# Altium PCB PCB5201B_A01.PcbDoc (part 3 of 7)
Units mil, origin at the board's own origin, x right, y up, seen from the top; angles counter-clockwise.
Board outline 4527.56 x 2362.2 mil, 6 copper layers (Top Layer, GND Layer 2, Signal Layer 3, Signal Layer 4, VCC Layer 5, Bottom Layer), stack 61.221 mil thick; 361 components, 250 nets, 1223 pads, 1068 vias.
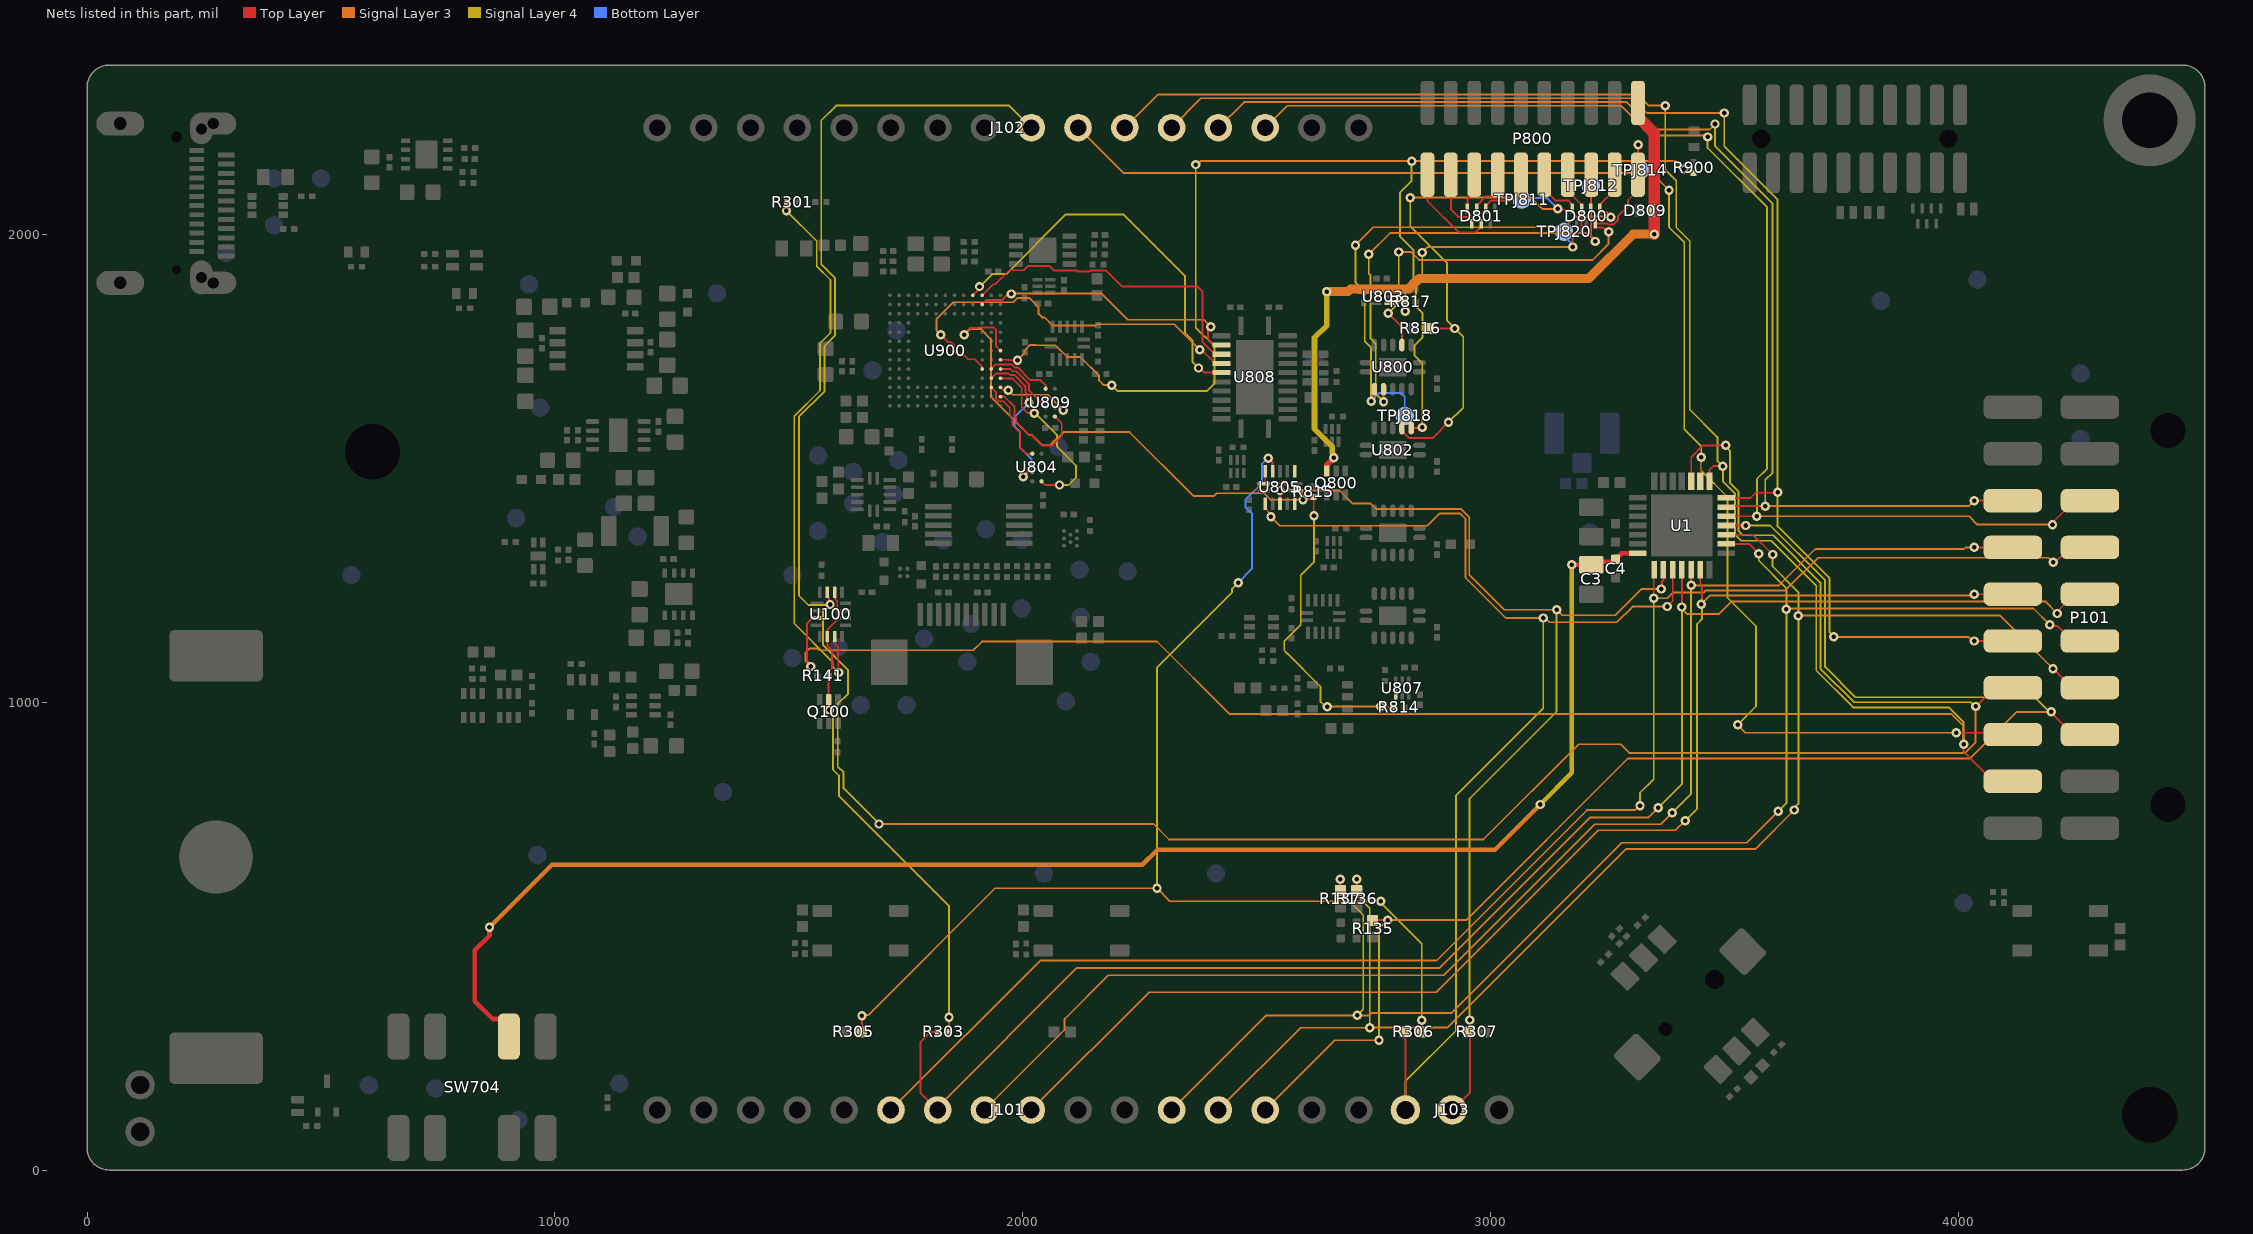
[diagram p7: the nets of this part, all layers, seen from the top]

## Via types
v1: diameter 20, hole 9.84, Top Layer to Bottom Layer, tented both sides, 1068 vias

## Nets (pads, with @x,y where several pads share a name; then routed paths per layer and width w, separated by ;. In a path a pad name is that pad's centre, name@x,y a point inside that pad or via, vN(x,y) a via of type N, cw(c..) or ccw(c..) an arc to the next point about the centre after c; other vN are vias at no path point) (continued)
DEBUG_DH_SW_ENABLE: R817.2 R900.1 U803.4 U900.F1 | length 2496.7
  Top Layer w3.94: U900.F1@1952.76,1732.28 1970.47,1732.28 1971.46,1731.3 1989.04,1731.3 v1(1989.11,1731.37) ; U803.4@2784.45,1853.35 2785.93,1854.82 2815.45,1854.82 R817.2@2817.91,1857.28 ; R817.2@2816.93,1856.3 2817.5,1855.72 2817.5,1836.91 v1(2818.08,1836.33) ; v1(3413.39,2139.76) 3414.86,2139.76 3423.11,2131.51 R900.1@3434.43,2131.51
  Signal Layer 3 w3.94: v1(1989.11,1731.37) 2004.7,1746.96 2004.7,1752.53 2016.2,1764.02 2027.14,1764.02 2027.81,1763.35 2070,1763.35 2095.16,1738.19 2123.11,1738.19 2163.39,1697.92 2163.39,1687.99 2173.23,1678.15 v1(2190.77,1678.15) ; v1(2370.08,2149.61) 2373.09,2149.61 2380.42,2156.94 v1(2831.64,2156.94) 3396.21,2156.94 v1(3413.39,2139.76)
  Signal Layer 4 w3.94: v1(2190.77,1678.15) 2203.56,1665.35 2394.11,1665.35 2410.43,1681.68 2410.43,1760.83 2370.08,1801.18 v1(2370.08,2149.61) ; v1@2815.94,1836.61 2818.19,1838.86 2818.19,1887.85 2835.35,1905.01 2835.35,1967.41 2807.09,1995.67 2807.09,2090.55 2831.64,2115.11 v1(2831.64,2156.94)
DEBUG_MCU_SW_ENABLE: R814.2 R815.2 U805.5 U805.6 U805.12 U805.13 U807.4 U900.G1 | length 1977.7
  Top Layer w3.94: v1(1875,1785.43) 1875,1787.4 1888.08,1800.48 1905.03,1800.48 1905.73,1801.18 1937.99,1801.18 1942.91,1796.26 1942.91,1761.81 U900.G1@1952.76,1751.97 ; U805.13@2515.35,1467.32 2518.7,1470.67 U805.12@2518.7,1494.29 ; U805.13@2517.52,1469.49 2557.09,1469.49 2575,1451.57 U805.6@2585.04,1451.57 ; U805.5@2581.69,1424.61 2581.69,1448.23 U805.6@2585.04,1451.57 ; v1(2623.03,1398.62) 2622.35,1399.31 2622.35,1437.98 R815.2@2621.66,1438.67 2621.66,1438.27 2617.33,1433.94 2600.28,1433.94 v1(2599.41,1433.07) 2598.61,1433.87 2598.61,1446.67 2596.46,1448.82 2596.46,1449.61 2594.49,1451.57 U805.6@2585.04,1451.57 ; v1(2765.75,991.14) 2766.63,990.26 2791.71,990.26 R814.2@2792.6,989.37 ; R814.2@2792.32,991.14 2794.76,991.14 2797.76,994.13 U807.4@2797.76,1016.73
  Signal Layer 3 w3.94: v1(1875,1785.43) 1887.8,1798.23 1910.43,1798.23 1932.09,1776.57 1932.09,1653.32 2014.26,1571.15 2020.17,1571.15 2041.82,1549.49 2059.44,1549.49 2087.7,1577.76 2228.49,1577.76 2365.02,1441.22 2409.73,1441.22 2415.35,1446.85 2516.17,1446.85 2529.95,1433.07 v1(2599.41,1433.07) ; v1@2654.53,991.14 2654.78,990.89 2765.5,990.89 v1(2765.75,991.14)
  Signal Layer 4 w3.94: v1(2623.03,1398.62) 2623.03,1300.2 2594.77,1271.93 2594.77,1165.63 2559.33,1130.2 2559.33,1110.72 2566,1104.05 2566.45,1104.05 2636.81,1033.69 2636.81,1000.98 2647.15,990.64 v1(2651.25,990.64)
DEBUG_RESET_#OE: U804.A1 U900.D1 | length 386.7
  Top Layer w3.94: U900.D1@1952.76,1692.91 1953.74,1691.93 1978.35,1691.93 1998.03,1672.24 1998.03,1630.91 2010.83,1618.11 v1(2024.61,1618.11) ; U804.A1@2040.35,1472.44 2048.23,1464.57 v1(2078.74,1464.57)
  Signal Layer 4 w3.94: v1(2024.61,1618.11) 2026.57,1618.11 2073.82,1570.87 2073.82,1546.48 2114.17,1506.13 2114.17,1480.32 2098.43,1464.57 v1(2078.74,1464.57)
DEBUG_TCK_SWCLK_#OE: U809.A1 U900.B1 | length 248.4
  Top Layer w3.94: U900.B1@1952.76,1653.54 1961.32,1653.54 1982.28,1632.58 1982.28,1613.19 1986.5,1608.97 1986.5,1598.91 1986.71,1598.7 1986.71,1597.93 2013.78,1570.87 2019.69,1570.87 2041.34,1549.21 2063.98,1549.21 2083.66,1568.9 2083.66,1596.46 U809.A1@2068.9,1611.22
DEBUG_TCK_SWCLK_C2CK: J103.2 R307.2 U1.9 U805.3 | length 2251.8
  Top Layer w3.94: U805.3@2550.2,1424.61 v1@2550.2,1446.85 ; J103.2@2918.5,128.43 2956.69,166.61 2956.69,295.28 2955.71,296.26 v1(2955.71,320.87) ; v1(3365.16,1242.13) 3366.79,1243.76 3366.79,1258.03 3370.08,1261.32 U1.9@3370.08,1288.39
  Signal Layer 3 w3.94: v1@2552.17,1452.76 2678.15,1452.76 2705.99,1424.92 2744.37,1424.92 2755.91,1413.39 2936.7,1413.39 2954.72,1395.36 2954.72,1272.64 3029.53,1197.83 v1(3141.73,1197.83) 3153.54,1186.02 3266.73,1186.02 3322.83,1242.13 v1(3365.16,1242.13)
  Signal Layer 4 w3.94: v1(2955.71,320.87) 2955.71,794.29 3141.73,980.32 v1(3141.73,1197.83)
  other v1: 2550.2,1452.76
DEBUG_TCK_SWCLK_IN: U808.4 U900.N3 | length 681.6
  Top Layer w3.94: U900.N3@1913.39,1870.08 1937.01,1893.7 1941.93,1893.7 1971.91,1923.68 1997.14,1923.68 1997.18,1923.73 2002.47,1923.73 2011.81,1933.07 2057.09,1933.07 2066.73,1923.43 2115.45,1923.43 2117.68,1921.19 2144.54,1921.19 2146.58,1923.23 2177.92,1923.23 2212.55,1888.6 2374.32,1888.6 2384.84,1878.08 2384.84,1769.69 2410.43,1744.09 U808.4@2425.39,1744.09
DEBUG_TCK_SWCLK_OUT: U809.B1 U900.C1 | length 175.8
  Top Layer w3.94: U900.C1@1952.76,1673.23 1958.66,1667.32 v1(1969.49,1667.32) v1@1970.47,1666.34 ; U809.B1@2068.9,1630.91 2076.28,1630.91 2082.67,1624.51 v1(2086.61,1624.51)
  Signal Layer 3 w3.94: v1(1969.49,1667.32) 1979.33,1657.48 2053.64,1657.48 v1(2086.61,1624.51)
DEBUG_TDI_#OE: U809.B2 U900.E1 | length 138.3
  Top Layer w3.94: U900.E1@1952.76,1712.6 1973.42,1712.6 1978.35,1707.68 1986.16,1707.68 2013.9,1679.94 2013.9,1666.22 U809.B2@2049.21,1630.91
DEBUG_TDI_C2DPS: R305.1 R306.1 U805.11 | length 2646.6
  Top Layer w3.94: R305.1@1655.51,295.28 1656.5,296.26 v1(1656.5,329.72) ; v1(2525.29,1521.64) 2526.05,1521.64 2534.45,1513.24 U805.11@2534.45,1494.29 ; R306.1@2851.38,295.28 2853.35,297.24 v1(2853.35,319.88)
  Signal Layer 3 w3.94: v1(1656.5,329.72) 1657.9,331.13 1669.71,331.13 1940.94,602.36 v1(2287.4,602.36) 2314.96,574.8 v1(2765.75,574.8)
  Signal Layer 4 w3.94: v1(2287.4,602.36) 2287.4,1074.8 2447.83,1235.24 2447.83,1243.11 v1(2460.63,1255.91) ; v1(2765.75,574.8) 2765.75,571.8 2853.35,484.2 v1(2853.35,319.88)
  Bottom Layer w3.94: v1(2460.63,1255.91) 2490.16,1285.43 2490.16,1402.56 ; 2490.65,1403.05 2476.38,1417.32 2476.38,1433.07 2511.81,1468.5 2511.81,1509.84 2523.61,1521.64 v1(2525.29,1521.64)
DEBUG_TDI_IN: U808.6 U900.N4 | length 844
  Top Layer w3.94: U900.N4@1893.7,1870.08 1907.91,1884.28 v1(1907.91,1888.78) ; v1(2376.12,1714.74) 2378.59,1714.74 2388.6,1704.72 U808.6@2425.39,1704.72
  Signal Layer 4 w3.94: v1(1907.91,1888.78) 1934.61,1915.48 1964.69,1915.48 2092.33,2043.12 2214.76,2043.12 2347.44,1910.43 2347.44,1789.37 2363.42,1773.39 2363.42,1727.44 v1(2376.12,1714.74)
DEBUG_TDI_OUT: U809.D2 U900.E2 | length 146.1
  Top Layer w3.94: U900.E2@1933.07,1712.6 1942.91,1722.44 1976.16,1722.44 1982.77,1715.83 1989.15,1715.83 2016.09,1688.88 2037.88,1688.88 2049.21,1677.55 U809.D2@2049.21,1670.28
DEBUG_TDO_SWO: U805.8
DEBUG_TDO_SWO_IN: U808.5 U900.E3 | length 863.7
  Top Layer w3.94: v1(1824.8,1785.43) 1840.55,1769.69 1847.25,1769.69 1853.74,1763.19 1853.74,1750.59 1863.19,1741.14 1875.79,1741.14 1883.67,1733.27 1897.64,1733.27 1913.39,1717.52 U900.E3@1913.39,1712.6 ; v1(2378.89,1753.41) 2382.41,1753.41 2411.42,1724.41 U808.5@2425.39,1724.41
  Signal Layer 3 w3.94: v1(1824.8,1785.43) 1815.94,1794.29 1815.94,1819.88 1851.38,1855.32 1980.09,1855.32 1988.94,1864.17 2015.09,1864.17 2034.29,1844.97 2034.29,1830.23 2041.69,1822.83 2046.74,1822.83 2064.18,1805.4 2155.48,1805.4 2158.16,1808.07 2324.23,1808.07 v1(2378.89,1753.41)
DEBUG_TMS_SWDIO_#OE: U804.B2 U900.D2 | length 346.3
  Top Layer w3.94: U900.D2@1933.07,1692.91 1942.91,1702.76 1970.47,1702.76 1973.43,1699.8 1982.28,1699.8 2006.03,1676.06 2006.03,1662.61 2008.86,1659.77 2008.86,1645.66 v1(2013.78,1640.75) ; v1@1999.02,1482.28 2008.86,1492.13 U804.B2@2020.67,1492.13
  Bottom Layer w3.94: v1(2000.98,1482.28) 2018.7,1500 2018.7,1520.67 1995.08,1544.29 1995.08,1577.76 1982.28,1590.55 1982.28,1609.25 v1(2013.78,1640.75)
DEBUG_TMS_SWDIO_C2D: J103.1 R306.2 U1.10 U805.1 | length 2508.2
  Top Layer w3.94: U805.1@2518.7,1424.61 2518.7,1414.37 v1@2530.9,1402.17 ; R306.2@2815.94,292.32 2818.5,289.76 J103.1@2818.5,128.43 2818.5,126.57 J103.1@2816.93,125 ; v1(3377.95,1204.72) 3389.76,1216.54 U1.10@3389.76,1288.39
  Signal Layer 3 w3.94: v1(2530.9,1396.81) 2550.2,1377.51 2864.72,1377.51 2890.75,1403.54 2935.41,1403.54 2946.85,1392.1 2946.85,1266.73 3033.46,1180.12 v1(3113.19,1180.12) 3117.54,1180.12 3126.39,1171.26 3270.67,1171.26 3304.13,1204.72 v1(3377.95,1204.72)
  Signal Layer 4 w3.94: J103.1@2818.5,128.43 2818.5,189.57 2926.18,297.24 2926.18,800.2 3113.19,987.2 v1(3113.19,1180.12)
DEBUG_TMS_SWDIO_IN: U808.3 U900.M3 | length 591.3
  Top Layer w3.94: U900.M3@1913.39,1850.39 1923.23,1860.24 1956.83,1860.24 1969.63,1873.03 v1(1975.39,1873.03) ; v1(2402.56,1803.15) 2396.65,1797.24 2396.65,1776.57 2409.45,1763.78 U808.3@2425.39,1763.78
  Signal Layer 3 w3.94: v1(1975.39,1873.03) 1976.24,1873.87 2169.21,1873.87 2225.17,1817.91 2387.8,1817.91 v1(2402.56,1803.15)
DEBUG_TMS_SWDIO_OUT: U804.D2 U900.C2 | length 191.3
  Top Layer w3.94: U900.C2@1933.07,1673.23 1942.91,1663.39 1942.91,1649.61 1942.91,1649.47 1948.68,1643.7 1958.58,1643.7 1972.44,1629.84 1972.44,1611.22 1978.35,1605.32 1978.35,1592.52 1995.08,1575.79 1995.08,1544.29 2007.87,1531.5 U804.D2@2020.67,1531.5
DEBUG_TRACECLK: D801.2 P800.12 | length 127.7
  Top Layer w3.94: D801.2@2990.16,2055.71 2990.16,2061.02 3001.97,2072.83 3043.31,2072.83 3065.55,2095.08 P800.12@3065.55,2127.95
DEBUG_TRACED0: D801.3 P800.14 | length 97.3
  Top Layer w3.94: D801.3@2970.47,2055.71 2970.47,2062.01 2990.16,2081.69 3000.98,2081.69 3015.55,2096.26 P800.14@3015.55,2127.95
DEBUG_TRACED1: D801.4 P800.16 | length 78.4
  Top Layer w3.94: D801.4@2950.79,2055.71 2950.79,2076.77 2965.55,2091.54 P800.16@2965.55,2127.95
DEBUG_TRACED2: D801.5 P800.18 | length 135.7
  Top Layer w3.94: P800.18@2915.55,2127.95 2915.55,2053.94 2932.09,2037.4 2952.76,2037.4 2960.63,2029.53 D801.5@2960.63,2023.03
DEBUG_TRACED3: D801.6 P800.20 | length 210
  Top Layer w3.94: P800.20@2865.55,2127.95 2865.55,2071.46 2932.09,2004.92 2968.5,2004.92 2980.32,2016.73 D801.6@2980.32,2023.03
DH_#RESET: D800.4 P800.10 R816.1 TPJ811.1 U802.3 | length 1278
  Top Layer w3.94: U802.3@2811.02,1586.61 2811.02,1580.71 2826.77,1564.96 2876.97,1564.96 v1(2910.43,1598.43) ; R816.1@2868.11,1799.21 v1@2920.28,1799.21 ; P800.10@3115.55,2127.95 3115.55,2096.06 3138.78,2072.83 3166.34,2072.83 3175.2,2063.98 D800.4@3175.2,2055.71 3172.64,2053.15 3145.52,2053.15 v1(3143.7,2054.96)
  Signal Layer 3 w3.94: v1(2828.74,2079.02) 3087.32,2079.02 3111.37,2054.96 v1(3143.7,2054.96)
  Signal Layer 4 w3.94: v1(2828.74,2079.02) 2828.74,2017.72 2907.48,1938.98 2907.48,1815.94 v1(2924.21,1799.21) 2941.93,1781.5 2941.93,1629.92 v1(2910.43,1598.43)
  Bottom Layer w3.94: TPJ811.1@3066.93,2074.8 3070.59,2078.46 3120.58,2078.46 3143.7,2055.34 v1(3143.7,2054.96)
DH_TCK_SWCLK: D800.1 P800.4 TPJ818.1 U800.9 | length 1191.4
  Top Layer w3.94: v1(2745.08,1643.7) 2745.08,1651.57 2751.97,1658.47 U800.9@2751.97,1669.29 ; v1(3257.17,2037.23) 3257.17,2039.23 3248.4,2047.99 3236.02,2047.99 3234.25,2049.76 3234.25,2063.98 3265.55,2095.28 P800.4@3265.55,2127.95
  Signal Layer 3 w3.94: v1(2711.61,1977.36) 2750,2015.75 3158.46,2015.75 3180.97,2038.26 3256.15,2038.26 v1(3257.17,2037.23)
  Signal Layer 4 w3.94: v1(2711.61,1977.36) 2711.61,1897.64 2731.3,1877.95 2731.3,1771.65 2745.08,1757.87 v1(2745.08,1643.7)
  Bottom Layer w3.94: v1(2745.08,1643.7) 2762.8,1661.42 2809.06,1661.42 2816.93,1653.54 TPJ818.1@2816.93,1612.2
DH_TDI: D800.3 P800.8 TPJ820.1 U802.2 | length 965.2
  Top Layer w3.94: U802.2@2830.71,1586.61 2853.35,1586.61 v1(2854.33,1587.6) ; P800.8@3165.55,2127.95 3165.55,2093.31 3194.88,2063.98 3194.88,2010.79 3175.39,1991.3 3175.39,1974.21 v1(3176.18,1973.43)
  Signal Layer 3 w3.94: v1(2854.33,1961.61) 2866.14,1973.43 v1(3176.18,1973.43)
  Signal Layer 4 w3.94: v1(2854.33,1587.6) 2854.33,1724.41 2837.88,1740.86 2837.88,1763.07 2855.04,1780.23 2855.04,1832.19 2841.22,1846.01 2841.22,1893.39 2854.33,1906.5 v1(2854.33,1961.61)
  Bottom Layer w3.94: TPJ820.1@3157.48,2005.91 3157.48,1996.47 3176.18,1977.77 v1(3176.18,1973.43)
DH_TDO_SWO: D800.2 P800.6 TPJ812.1 U800.10 | length 1131.4
  Top Layer w3.94: v1@2771.65,1646.65 U800.10@2771.65,1669.29 ; P800.6@3215.55,2127.95 3214.57,2126.97 D800.2@3214.57,2055.71 3214.57,1997.89 3224.41,1988.05 v1(3224.41,1985.24)
  Signal Layer 3 w3.94: v1(2740.16,1957.68) 2785.43,2002.95 3206.69,2002.95 v1(3224.41,1985.24)
  Signal Layer 4 w3.94: v1(2740.16,1957.68) 2740.16,1916.56 2743.82,1912.9 2743.82,1777.84 2754.92,1766.73 2754.92,1659.45 v1(2771.65,1642.72)
  Bottom Layer w3.94: TPJ812.1@3214.57,2104.33 3214.57,1997.89 3224.41,1988.05 v1(3224.41,1985.24)
DH_TMS_SWDIO: D800.7 P800.2 TPJ814.1 U800.3 | length 1046.4
  Top Layer w3.94: v1(2782.01,1831.76) 2811.02,1802.74 U800.3@2811.02,1763.78 ; v1(3252.88,2006.3) 3248.98,2006.3 3239.96,2015.31 3226.18,2015.31 3224.41,2017.09 3224.41,2025.39 3226.18,2023.62 3249.02,2023.62 3250.87,2021.76 3263.69,2021.76 3272.75,2030.83 3272.75,2039.48 3294.29,2061.02 3294.29,2073.82 3315.55,2095.08 P800.2@3315.55,2127.95 3315.55,2191.54 v1(3315.94,2191.93)
  Signal Layer 3 w3.94: v1(2804.13,1962.6) 2830.68,1962.6 2847.69,1945.59 3218.59,1945.59 3252.88,1979.88 v1(3252.88,2006.3)
  Signal Layer 4 w3.94: v1(2782.01,1831.76) 2804.13,1853.88 v1(2804.13,1962.6)
  Bottom Layer w3.94: v1(3315.94,2191.93) 3315.94,2142.72 TPJ814.1@3320.87,2137.8
DH_VTREF: D809.1 P800.1 Q800.3 | length 1464.6
  Top Layer w11.81: Q800.3@2650.59,1494.09 2650.59,1507.87 v1(2665.35,1522.64)
  Top Layer w25: P800.1@3315.55,2281.5 3315.55,2251.71 3350.39,2216.87 v1(3350.39,2000.98)
  Signal Layer 3 w19.68: v1(2650.31,1878.02) 2695.4,1878.02 2701.24,1883.86 2717.97,1883.86 2718.68,1883.15 2738.02,1883.15 2738.72,1883.86 2825.83,1883.86 2847.97,1906 3210.14,1906 3305.12,2000.98 v1(3350.39,2000.98)
  Signal Layer 4 w11.81: v1(2650.31,1878.02) 2650.31,1805.82 2624.02,1779.53 2624.02,1584.65 2661.82,1546.84 2661.82,1531.96 2663.79,1530 2663.79,1524.2 v1(2665.35,1522.64)
  Bottom Layer w19.68: v1(2650.31,1878.02) v1(2650.31,1878.02)
DISP_CS: R301.1 U100.7 | length 1198.1
  Top Layer w3.94: v1(1495.08,2051.18) 1495.57,2051.67 1495.57,2067.42 R301.1@1498.03,2069.88 ; U100.7@1598.03,1140.75 1598.03,1125.15 1605.91,1117.27 1605.91,1064.51 v1(1606.58,1063.83)
  Signal Layer 4 w3.94: v1(1495.08,2051.18) 1560.04,1986.22 1560.04,1932.09 1589.29,1902.84 1589.29,1790.07 1566.88,1767.66 1566.88,1666.61 1511.81,1611.54 1511.81,1168.4 1593.32,1086.89 1593.32,1077.1 v1(1606.58,1063.83)
DISP_ENABLE: Q100.2 R141.2 R303.1 U100.6 U100.14 | length 1066
  Top Layer w3.94: v1(1586.49,983.47) 1586.06,983.9 1586.06,1005.07 1584.49,1006.63 1584.98,1007.12 1584.98,1055.73 R141.2@1584.34,1056.38 1584.43,1056.47 1584.43,1064.53 1592.24,1072.34 1592.24,1111.5 1582.68,1121.06 1582.68,1140.35 U100.6@1582.28,1140.75 1582.98,1141.45 1582.98,1155.82 1603.82,1176.65 1603.82,1216.05 1600,1219.87 1600,1233.27 U100.14@1598.03,1235.24 ; R303.1@1842.52,295.28 v1(1842.52,326.77)
  Signal Layer 4 w3.94: v1(1586.49,983.47) 1586.49,981.14 1594.49,973.13 1594.49,856.3 1607.28,843.5 1607.28,800.2 1842.52,564.96 v1(1842.52,326.77)
DISP_SCLK: J102.9 P101.8 U1.24 U100.15 | length 5925.8
  Top Layer w3.94: U100.15@1582.28,1235.24 1584.25,1233.27 1584.25,1223.82 1586.39,1221.68 1586.39,1210.96 v1(1588.35,1209.01) ; U1.24@3429.13,1467.52 3429.63,1468.01 3429.63,1524.34 3454.5,1549.21 v1(3502.95,1549.21) ; v1(4037.4,991.14) 4038.44,991.14 4078.4,1031.1 P101.8@4116.93,1031.1
  Signal Layer 3 w3.94: v1(1693.03,739.89) 2279.79,739.89 2312.99,706.69 2985.24,706.69 3188.7,910.15 3278.82,910.15 3297.24,891.73 4014.99,891.73 4037.4,914.15 v1(4037.4,991.14)
  Signal Layer 4 w3.94: v1@1587.13,1207.79 1542.21,1207.79 1521.65,1228.35 1521.65,1610.25 1576.77,1665.37 1576.77,1761.81 1599.2,1784.24 1599.2,1906.7 1569.54,1936.36 1569.54,2243.76 1601.38,2275.59 1971.34,2275.59 J102.9@2018.5,2228.43 ; v1(1588.35,1209.01) 1572.88,1193.54 1572.88,1122.99 1626.97,1068.9 1626.97,1018.7 1604.85,996.59 1604.85,862.67 1617.13,850.39 1617.13,815.79 v1(1693.03,739.89) ; v1(3502.95,1549.21) 3502.95,1545.84 3512.52,1536.28 3512.52,1498.51 3512.09,1498.09 3512.09,1468.99 3530.79,1450.29 3530.79,1365.86 3539.37,1357.28 3604.33,1357.28 3705.71,1255.91 3705.71,1071.85 3777.56,1000 4027.06,1000 4035.92,991.14 v1(4037.4,991.14)
DISP_SI: J102.11 P101.4 U1.22 U100.3 | length 5944
  Top Layer w3.94: 1544.87,1174.21 1539.35,1168.7 1539.35,1088.82 1547.38,1080.79 v1(1547.38,1076.44) ; 1544.88,1174.21 1550.79,1180.12 U100.3@1558.66,1180.12 ; U1.22@3468.5,1467.52 3468.5,1497.05 3476.38,1504.92 v1@3494.09,1504.92 ; v1(4011.81,910.43) 4011.81,894.69 4075.39,831.1 P101.4@4116.93,831.1
  Signal Layer 3 w3.94: v1(1547.38,1076.44) 1535.43,1088.39 1535.43,1106.3 1544.01,1114.88 1561.84,1114.88 1565.5,1111.22 1894.69,1111.22 1913.39,1129.92 2287.31,1129.92 2442.06,975.18 3985.46,975.18 4011.81,948.82 v1(4011.81,910.43) ; J102.11@2218.5,2228.43 2289.23,2299.15 3315.02,2299.15 3338.58,2275.59 v1(3374.02,2275.59)
  Signal Layer 4 w3.94: v1(3374.02,2275.59) 3374.02,2138.47 3397.36,2115.13 3397.36,2015.04 3426.18,1986.22 3426.18,1625.98 3485.24,1566.93 3485.24,1516.73 v1(3497.05,1504.92) 3497.05,1472.89 3522.92,1447.02 3522.92,1358.97 3536.42,1345.47 3600.62,1345.47 3696.85,1249.24 3696.85,1067.91 3775.59,989.17 3980.32,989.17 4011.81,957.68 v1(4011.81,910.43)
EFM_VREGIN: C3.1 C4.1 SW704.2 U1.7 | length 3334.3
  Top Layer w9.84: v1(860.24,518.7) 860.24,500.98 828.74,469.49 828.74,361.22 867.04,322.92 883.4,322.92 901.58,304.75 SW704.2@901.58,285.43 ; v1(3174.21,1294.29) 3174.32,1294.18 3215.44,1294.18 C3.1@3215.55,1294.07 ; C3.1@3217.52,1303.15 3220.01,1300.66 3262.8,1300.66 C4.1@3267.72,1305.58 3281.03,1318.9 U1.7@3319.88,1318.9
  Signal Layer 3 w9.84: v1(860.24,518.7) 993.82,652.28 2255.63,652.28 2288.39,685.04 3009.84,685.04 v1(3106.3,781.5)
  Signal Layer 4 w9.84: v1(3106.3,781.5) 3174.21,849.41 v1(3174.21,1294.29)
EXP_HEADER5: J101.14 P101.5 R135.2 U1.18 | length 3282.3
  Top Layer w3.94: R135.2@2748.03,533.46 2750,535.43 2751.1,534.34 v1(2780.62,534.34) ; U1.18@3499.02,1377.95 v1(3546.26,1377.95) ; v1(4199.13,979.55) 4199.13,977.96 4245.98,931.1 P101.5@4281.89,931.1
  Signal Layer 3 w3.94: J101.14@2518.5,128.43 2667.64,277.56 v1(2761.81,277.56) ; v1(2780.62,534.34) 2948.71,534.34 3294.29,879.92 4025.59,879.92 4125.22,979.55 v1(4199.13,979.55)
  Signal Layer 4 w3.94: v1(2761.81,277.56) 2761.81,515.53 v1(2780.62,534.34) ; v1(3546.26,1377.95) 3598.43,1377.95 3715.55,1260.83 3715.55,1075.79 3780.51,1010.83 4163.39,1010.83 4191.59,982.62 4191.71,982.62 v1@4196.85,977.48
EXP_HEADER6: J102.10 P101.6 U1.23 | length 3209
  Top Layer w3.94: U1.23@3448.82,1467.52 3450.79,1469.49 v1(3450.79,1523.62) ; v1(3996.06,935.04) 4112.99,935.04 P101.6@4116.93,931.1
  Signal Layer 3 w3.94: J102.10@2118.5,2228.43 2215.04,2131.89 3344.77,2131.89 v1(3381.89,2094.77) ; v1(3528.54,951.77) 3545.34,934.98 3996,934.98 v1(3996.06,935.04)
  Signal Layer 4 w3.94: v1(3381.89,2094.77) 3381.89,2015.75 3414.37,1983.27 3414.37,1583.66 3450.79,1547.24 v1(3450.79,1523.62) 3450.79,1495.08 3506.99,1438.88 3506.99,1223.33 3567.91,1162.4 3567.91,991.14 v1(3528.54,951.77)
EXP_HEADER7: J101.13 P101.7 R136.2 U1.17 | length 3232.8
  Top Layer w3.94: R136.2@2714.31,597.81 2714.57,598.07 v1(2714.57,622.05) ; U1.17@3499.02,1358.27 3561.02,1358.27 v1(3603.35,1315.94) ; v1(4202.87,1072.01) 4203.18,1072.01 4244.08,1031.1 P101.7@4281.89,1031.1
  Signal Layer 3 w3.94: J101.13@2418.5,128.43 2594.21,304.13 v1(2742.13,304.13) 2742.41,304.41 2907.76,304.41 3289.37,686.02 3565.94,686.02 v1(3649.61,769.69) ; v1(3658.46,1185.04) 3659.17,1185.74 4089.13,1185.74 v1(4202.87,1072.01)
  Signal Layer 4 w3.94: v1(2714.57,622.05) 2714.57,587.6 2742.13,560.04 v1(2742.13,304.13) ; v1(3603.35,1315.94) 3603.35,1290.35 3658.46,1235.24 v1(3658.46,1185.04) 3658.46,782.89 3649.61,774.03 v1(3649.61,769.69)
EXP_HEADER9: J101.12 P101.9 R137.2 U1.16 | length 3245.1
  Top Layer w3.94: v1(2679.13,622.05) 2679.13,598 R137.2@2679.2,597.93 ; U1.16@3499.02,1338.58 3553.15,1338.58 v1(3573.82,1317.91) ; v1(4196.21,1165.43) 4198.26,1163.38 4212.11,1163.38 4244.39,1131.1 P101.9@4281.89,1131.1
  Signal Layer 3 w3.94: J101.12@2318.5,128.43 2520.79,330.71 v1(2715.55,330.71) v1@2716.54,330.71 ; v1@2718.5,330.71 2741.14,330.71 2746.06,335.63 2916.34,335.63 3280.51,699.8 3548.23,699.8 v1(3615.16,766.73) ; v1(3632.87,1198.82) 3634.56,1200.51 4161.13,1200.51 v1(4196.21,1165.43)
  Signal Layer 4 w3.94: v1(2679.13,622.05) 2679.13,594.49 2728.35,545.28 2728.35,343.5 v1(2715.55,330.71) ; v1(3573.82,1317.91) 3573.82,1303.15 3632.87,1244.09 v1(3632.87,1198.82) 3632.87,784.45 v1(3615.16,766.73)
EXP_HEADER10: J102.12 P101.10 U1.21 | length 2943.9
  Top Layer w3.94: U1.21@3499.02,1437.01 3556.1,1437.01 3566.93,1447.83 3613.19,1447.83 v1(3614.17,1448.82) ; v1(4034.25,1131.1) P101.10@4116.93,1131.1
  Signal Layer 3 w3.94: J102.12@2318.5,2228.43 2381.29,2291.21 3303.28,2291.21 3334.65,2259.84 v1(3500,2259.84) ; v1(3734.25,1139.76) 4021.24,1139.76 4029.91,1131.1 v1(4034.25,1131.1)
  Signal Layer 4 w3.94: v1(3500,2259.84) 3500,2188.77 3614.17,2074.6 v1(3614.17,1448.82) 3614.17,1375.98 3725.39,1264.76 3725.39,1150.1 3734.25,1141.24 v1(3734.25,1139.76)
EXP_HEADER11: J101.7 P101.11 R303.2 U1.11 | length 3475.7
  Top Layer w3.94: J101.7@1818.5,128.43 1781.5,165.43 1781.5,273.62 1803.15,295.28 R303.2@1818.9,295.28 ; v1(3409.45,1203.74) U1.11@3409.45,1288.39 ; v1(4211.7,1189.83) 4211.7,1194.12 4248.68,1231.1 P101.11@4281.89,1231.1
  Signal Layer 3 w3.94: J101.7@1818.5,128.43 1818.5,134.45 2116.14,432.09 2891.73,432.09 3213.58,753.94 3338.58,753.94 v1(3359.25,774.61) ; v1(3409.45,1203.74) 3409.45,1199.49 3419.96,1188.98 3489.17,1188.98 3515.75,1215.55 4185.98,1215.55 v1(4211.7,1189.83)
  Signal Layer 4 w3.94: v1(3359.25,774.61) 3409.45,824.8 v1(3409.45,1203.74)
EXP_HEADER12: J101.9 P101.12 U1.13 | length 2888.8
  Top Layer w3.94: U1.13@3448.82,1288.39 3448.82,1254.92 3452.76,1250.98 3452.76,1211.61 v1(3450.79,1209.65) ; v1(4034.25,1231.1) P101.12@4116.93,1231.1
  Signal Layer 3 w3.94: J101.9@2018.5,128.43 2270.28,380.2 2884.14,380.2 3230.32,726.38 3395.67,726.38 v1(3416.34,747.05) ; v1(3450.79,1209.65) 3469.17,1228.03 4031.18,1228.03 v1(4034.25,1231.1)
  Signal Layer 4 w3.94: v1(3416.34,747.05) 3441.93,772.64 3441.93,1167.32 3452.76,1178.15 3452.76,1207.68 v1(3450.79,1209.65)
EXP_HEADER13: J101.6 P101.13 U1.8 | length 3376.7
  Top Layer w3.94: v1(3349.41,1222.44) 3349.41,1287.4 U1.8@3350.39,1288.39 ; v1(4203.74,1299.21) 4208.09,1299.21 4241.95,1333.07 P101.13@4283.46,1333.07
  Signal Layer 3 w3.94: J101.6@1718.5,128.43 2037.91,447.83 2884.84,447.83 3206.69,769.69 3309.54,769.69 3318.4,778.54 v1(3319.88,778.54) ; v1@3354.33,1221.46 3355.31,1222.44 3377.95,1222.44 3390.04,1234.53 3455.99,1234.53 3460.63,1239.17 3630.91,1239.17 3700.79,1309.06 4193.9,1309.06 v1(4203.74,1299.21)
  Signal Layer 4 w3.94: v1(3319.88,778.54) 3319.88,806.28 3349.41,835.81 v1(3349.41,1222.44)
EXP_HEADER14: J101.8 P101.14 U1.12 | length 3007.9
  Top Layer w3.94: v1(3429.13,1250) U1.12@3429.13,1288.39 ; v1(4034.25,1331.1) P101.14@4116.93,1331.1
  Signal Layer 3 w3.94: J101.8@1918.5,128.43 2089.57,299.49 2089.57,322.83 2183.07,416.34 2900.59,416.34 3223.43,739.17 3364.17,739.17 v1(3388.78,763.78) ; v1(3429.13,1250) 3617.13,1250 3694.88,1327.76 4012.8,1327.76 4016.14,1331.1 v1(4034.25,1331.1)
  Signal Layer 4 w3.94: v1(3388.78,763.78) 3429.13,804.13 v1@3429.13,1248.03
EXP_HEADER15: J102.14 P101.15 U1.19 | length 2682
  Top Layer w3.94: U1.19@3499.02,1397.64 v1(3569.88,1397.64) ; v1(4201.77,1379.92) 4201.77,1384.2 4250.64,1433.07 P101.15@4283.46,1433.07
  Signal Layer 3 w3.94: J102.14@2518.5,2228.43 2565.42,2275.34 3279.78,2275.34 3343.39,2211.73 3461.5,2211.73 v1(3464.57,2208.66) ; v1(3569.88,1397.64) 4023.62,1397.64 4041.34,1379.92 v1(4201.77,1379.92)
  Signal Layer 4 w3.94: v1(3464.57,2208.66) 3464.57,2185.04 3591.54,2058.07 3591.54,1499.02 3569.88,1477.36 v1(3569.88,1397.64)
EXP_HEADER16: J102.13 P101.16 U1.20 | length 2611.8
  Top Layer w3.94: U1.20@3499.02,1417.32 3500.98,1419.29 v1(3587.6,1419.29) ; v1(4034.25,1431.1) P101.16@4116.93,1431.1
  Signal Layer 3 w3.94: J102.13@2418.5,2228.43 2473.35,2283.28 3291.53,2283.28 3350.39,2224.41 3468.5,2224.41 v1(3480.32,2236.22) ; v1(3587.6,1419.29) 4022.44,1419.29 v1(4034.25,1431.1)
  Signal Layer 4 w3.94: v1(3480.32,2236.22) 3480.32,2188.98 3603.35,2065.94 3603.35,1491.14 3587.6,1475.39 v1(3587.6,1419.29)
